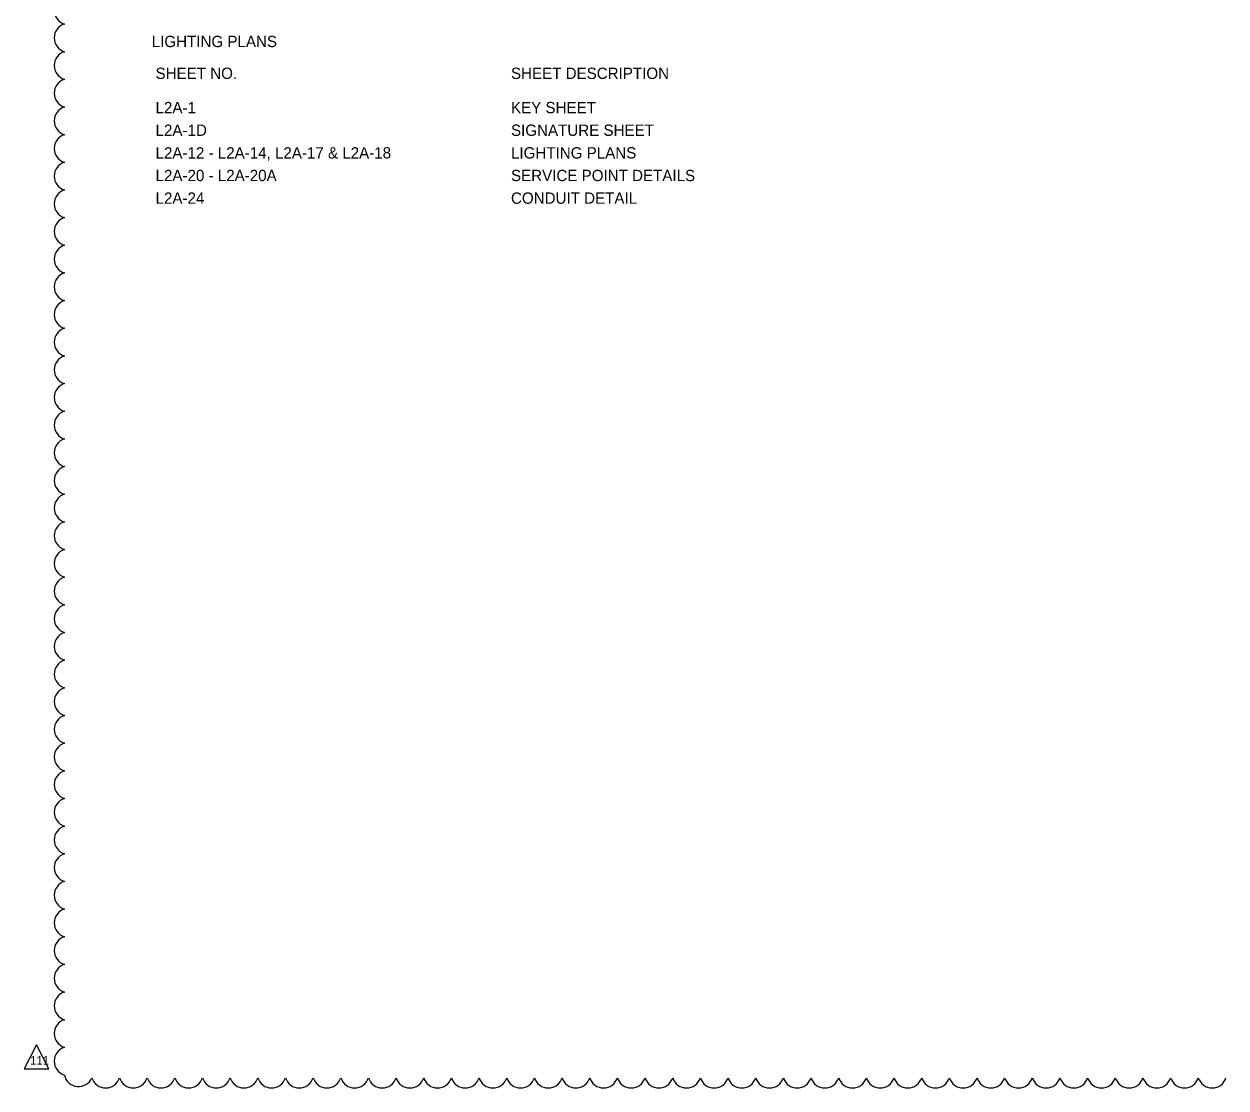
# Model space of a CAD drawing. Extents: x -811 to 10319, y -2309 to 9962.
# Drawn here: x -811.04 to -803.6, y -2244.74 to -2238.16 of the extents above; entities that cross this region are included whole.
import ezdxf

# ---------------------------------------------------------------- set-up
doc = ezdxf.new("R2010")
doc.units = 0
for name, color, linetype in [('PlotBorder_dp', 7, 'Continuous'), ('TextMisc', 7, 'Continuous'), ('TextTitle', 7, 'Continuous')]:
    doc.layers.add(name, color=color, linetype=linetype)

msp = doc.modelspace()

# ---------------------------------------------------------------- linework, layer by layer
at = {"layer": 'TextMisc'}
msp.add_lwpolyline([(-810.9581, -2244.4756), (-811.0351, -2244.624), (-810.8811, -2244.624)], close=True, dxfattribs=at)
at = {"layer": 'TextTitle'}
for centre, radius, start, end in [((-810.7588, -2238.0739), 0.0897, 107.5, 252.5), ((-810.7588, -2238.245), 0.0897, 107.5, 252.5), ((-810.7588, -2238.4161), 0.0897, 107.5, 252.5), ((-810.7588, -2238.5872), 0.0897, 107.5, 252.5), ((-810.7588, -2238.7584), 0.0897, 107.5, 252.5), ((-810.7588, -2238.9295), 0.0897, 107.5, 252.5), ((-810.7588, -2239.1006), 0.0897, 107.5, 252.5), ((-810.7588, -2239.2717), 0.0897, 107.5, 252.5), ((-810.7588, -2239.4429), 0.0897, 107.5, 252.5), ((-810.7588, -2239.614), 0.0897, 107.5, 252.5), ((-810.7588, -2239.7851), 0.0897, 107.5, 252.5), ((-810.7588, -2239.9562), 0.0897, 107.5, 252.5), ((-810.7588, -2240.1273), 0.0897, 107.5, 252.5), ((-810.7588, -2240.2985), 0.0897, 107.5, 252.5), ((-810.7588, -2240.4696), 0.0897, 107.5, 252.5), ((-810.7588, -2240.6407), 0.0897, 107.5, 252.5), ((-810.7588, -2240.8118), 0.0897, 107.5, 252.5), ((-810.7588, -2240.983), 0.0897, 107.5, 252.5), ((-810.7588, -2241.1541), 0.0897, 107.5, 252.5), ((-810.7588, -2241.3252), 0.0897, 107.5, 252.5), ((-810.7588, -2241.4963), 0.0897, 107.5, 252.5), ((-810.7588, -2241.6675), 0.0897, 107.5, 252.5), ((-810.7588, -2241.8386), 0.0897, 107.5, 252.5), ((-810.7588, -2242.0097), 0.0897, 107.5, 252.5), ((-810.7588, -2242.1808), 0.0897, 107.5, 252.5), ((-810.7588, -2242.3519), 0.0897, 107.5, 252.5), ((-810.7588, -2242.5231), 0.0897, 107.5, 252.5), ((-810.7588, -2242.6942), 0.0897, 107.5, 252.5), ((-810.7588, -2242.8653), 0.0897, 107.5, 252.5), ((-810.7588, -2243.0364), 0.0897, 107.5, 252.5), ((-810.7588, -2243.2076), 0.0897, 107.5, 252.5), ((-810.7588, -2243.3787), 0.0897, 107.5, 252.5), ((-810.7588, -2243.5498), 0.0897, 107.5, 252.5), ((-810.7588, -2243.7209), 0.0897, 107.5, 252.5), ((-810.7588, -2243.892), 0.0897, 107.5, 252.5), ((-810.7588, -2244.0632), 0.0897, 107.5, 252.5), ((-810.7588, -2244.2343), 0.0897, 107.5, 252.5), ((-810.7588, -2244.4054), 0.0897, 107.5, 252.5), ((-810.7588, -2244.5765), 0.0897, 107.5, 252.5), ((-810.698, -2244.6438), 0.0896, 191.74536, 336.74536), ((-810.5301, -2244.6523), 0.0897, 197.5, 342.5), ((-810.359, -2244.6523), 0.0897, 197.5, 342.5), ((-810.1879, -2244.6523), 0.0897, 197.5, 342.5), ((-810.0167, -2244.6523), 0.0897, 197.5, 342.5), ((-809.8456, -2244.6523), 0.0897, 197.5, 342.5), ((-809.6745, -2244.6523), 0.0897, 197.5, 342.5), ((-809.5034, -2244.6523), 0.0897, 197.5, 342.5), ((-809.3323, -2244.6523), 0.0897, 197.5, 342.5), ((-809.1611, -2244.6523), 0.0897, 197.5, 342.5), ((-808.99, -2244.6523), 0.0897, 197.5, 342.5), ((-808.8189, -2244.6523), 0.0897, 197.5, 342.5), ((-808.6478, -2244.6523), 0.0897, 197.5, 342.5), ((-808.4766, -2244.6523), 0.0897, 197.5, 342.5), ((-808.3055, -2244.6523), 0.0897, 197.5, 342.5), ((-808.1344, -2244.6523), 0.0897, 197.5, 342.5), ((-807.9633, -2244.6523), 0.0897, 197.5, 342.5), ((-807.7921, -2244.6523), 0.0897, 197.5, 342.5), ((-807.621, -2244.6523), 0.0897, 197.5, 342.5), ((-807.4499, -2244.6523), 0.0897, 197.5, 342.5), ((-807.2788, -2244.6523), 0.0897, 197.5, 342.5), ((-807.1077, -2244.6523), 0.0897, 197.5, 342.5), ((-806.9365, -2244.6523), 0.0897, 197.5, 342.5), ((-806.7654, -2244.6523), 0.0897, 197.5, 342.5), ((-806.5943, -2244.6523), 0.0897, 197.5, 342.5), ((-806.4232, -2244.6523), 0.0897, 197.5, 342.5), ((-806.252, -2244.6523), 0.0897, 197.5, 342.5), ((-806.0809, -2244.6523), 0.0897, 197.5, 342.5), ((-805.9098, -2244.6523), 0.0897, 197.5, 342.5), ((-805.7387, -2244.6523), 0.0897, 197.5, 342.5), ((-805.5676, -2244.6523), 0.0897, 197.5, 342.5), ((-805.3964, -2244.6523), 0.0897, 197.5, 342.5), ((-805.2253, -2244.6523), 0.0897, 197.5, 342.5), ((-805.0542, -2244.6523), 0.0897, 197.5, 342.5), ((-804.8831, -2244.6523), 0.0897, 197.5, 342.5), ((-804.7119, -2244.6523), 0.0897, 197.5, 342.5), ((-804.5408, -2244.6523), 0.0897, 197.5, 342.5), ((-804.3697, -2244.6523), 0.0897, 197.5, 342.5), ((-804.1986, -2244.6523), 0.0897, 197.5, 342.5), ((-804.0275, -2244.6523), 0.0897, 197.5, 342.5), ((-803.8563, -2244.6523), 0.0897, 197.5, 342.5), ((-803.6852, -2244.6523), 0.0897, 197.5, 342.5)]:
    msp.add_arc(centre, radius, start, end, dxfattribs=at)

# ---------------------------------------------------------------- texts
at = {"layer": 'PlotBorder_dp'}
msp.add_text('LIGHTING PLANS', height=0.07, dxfattribs=at).set_placement((-810.245, -2238.3022))
at = {"layer": 'TextMisc'}
for s, p in [('SHEET NO.', (-810.2215, -2238.4992)), ('SHEET DESCRIPTION', (-808.0226, -2238.4992)), ('L2A-1', (-810.2215, -2238.7114)), ('KEY SHEET', (-808.0226, -2238.7114)), ('L2A-1D', (-810.2215, -2238.8514)), ('SIGNATURE SHEET', (-808.0226, -2238.8514)), ('L2A-12 - L2A-14, L2A-17 & L2A-18', (-810.2215, -2238.9914)), ('LIGHTING PLANS', (-808.0226, -2238.9914)), ('L2A-20 - L2A-20A', (-810.2215, -2239.1314)), ('SERVICE POINT DETAILS', (-808.0226, -2239.1314)), ('L2A-24', (-810.2215, -2239.2714)), ('CONDUIT DETAIL', (-808.0226, -2239.2714))]:
    msp.add_text(s, height=0.07, dxfattribs=at).set_placement(p)
msp.add_text('111', height=0.0525, rotation=360, dxfattribs=at).set_placement((-810.9978, -2244.5976))

doc.saveas('drawing.dxf')
